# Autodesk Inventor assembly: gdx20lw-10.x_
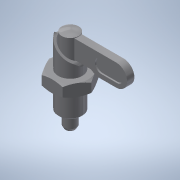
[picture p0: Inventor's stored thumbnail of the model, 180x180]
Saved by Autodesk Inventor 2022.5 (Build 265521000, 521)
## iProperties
Part Number: gdx20lw-10.x_
Material: 一般
Document SubType Name: Assembly
Designer: ImaoCorp
Sending System: SOLIDWORKS 2017-2017317
MC: AMD64
MC_MODEL: Intel64 Family 6 Model 60 Stepping 3, GenuineIntel
OS: Windows_NT
FRU: Parasolid Version 29.0, build 201,  4-17-2017
FORMAT: text
GUISE: transmit
KEY: gdx20lw-10
FILE: gdx20lw-10.x_t
DATE: Mon Jul 01 17:35:31 2019
Author: ImaoCorp
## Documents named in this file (3)
- X:\14_SW2022-Inv2022\00_全2023-1023新製品(TCC)まで\g\gdx20lw-10\GDX20LW-10.iam
- X:\14_SW2022-Inv2022\00_全2023-1023新製品(TCC)まで\g\gdx20lw-10\gdx20lw-10_01.ipt
- X:\14_SW2022-Inv2022\00_全2023-1023新製品(TCC)まで\g\gdx20lw-10\gdx20lw-10_02.ipt
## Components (2 placed, 2 different names)
1. gdx20lw-10_01
2. gdx20lw-10_02
